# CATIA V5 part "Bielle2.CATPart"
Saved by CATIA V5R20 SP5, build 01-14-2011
Part number: bielle2
Bounding box of the stored display mesh (mm): x 0 to 50, y -117.061 to 1.684, z -0.806 to 19.189
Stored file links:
  U:\IAO_projet\Bielle2.CATPart
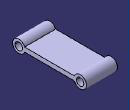
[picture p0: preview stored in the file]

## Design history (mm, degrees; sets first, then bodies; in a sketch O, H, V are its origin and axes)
Body1 (main body)
  Sketch1 on yz-plane, origin (0, 0, 0), H (0, 1, 0), V (0, 0, 1)
    line L1 (-97.6882, 12.6779) -> (-17.6882, 12.6779)
    line L2 (-17.6882, 5.705) -> (-97.6882, 5.705)
    arc A1 centre (-8.3157, 9.1915) radius 10 from (-17.6882, 12.6779) to (-17.6882, 5.705) cw
    arc A2 centre (-107.0608, 9.1915) radius 10 from (-97.6882, 12.6779) to (-97.6882, 5.705) ccw
    point P7 (-111, 0)
    circle A3 centre (-8.3157, 9.1915) radius 6
    circle A4 centre (-107.0608, 9.1915) radius 6
    radius A2 = 10
    length L1 = 80
    length L2 = 80
    horizontal: L1 H, L2 H
    coincidence: A2 P7, P7 H
  Pad1: profile Sketch1, direction (1, 0, 0), length 50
